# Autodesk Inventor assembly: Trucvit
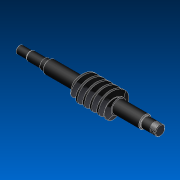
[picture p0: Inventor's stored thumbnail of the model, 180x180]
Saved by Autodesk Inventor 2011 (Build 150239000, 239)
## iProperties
Created: 2011-05
Part Number: Trucvit
Document SubType Name: Assembly
Designer: 904Chiaki
Author: 904Chiaki
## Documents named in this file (3)
- E:\2.FINISH\DOAN_CTM_final\Trucvit.iam
- E:\2.FINISH\DOAN_CTM_final\Shaft2.ipt
- E:\2.FINISH\DOAN_CTM_final\Worm1.ipt
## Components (2 placed, 2 different names)
1. Worm:1 — Mate:1, Flush:1
2. Shaft:1 — Mate:1, Flush:1
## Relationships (2: Mate 1, Flush 1)
- Mate:1: Worm:1 ↔ Shaft:1
- Flush:1: Worm:1 ↔ Shaft:1
